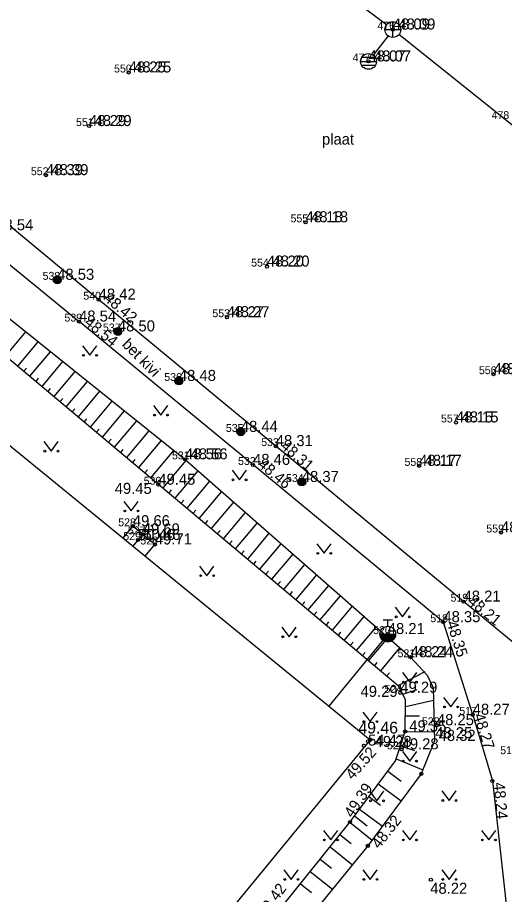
# Model space of a CAD drawing. Extents: x 640876 to 641418, y 6455595 to 6456085.
# Drawn here: x 641167 to 641197.9, y 6455921.6 to 6455977.1 of the extents above; entities that cross this region are included whole.
import ezdxf

# ---------------------------------------------------------------- set-up
doc = ezdxf.new("R2010")
doc.units = 0
for name, color, linetype in [('HALJASTUS', 7, 'Continuous'), ('HOONE', 7, 'Continuous'), ('HOONEDET', 7, 'Continuous'), ('KKAEV', 7, 'Continuous'), ('KORGUS', 7, 'Continuous'), ('MOOTKORG', 7, 'Continuous'), ('MOOTMPUNKT', 7, 'Continuous'), ('MOOTNR', 7, 'Continuous'), ('RAJATIS', 7, 'Continuous'), ('RELJEEF', 7, 'Continuous'), ('SKKAEV', 7, 'Continuous'), ('SKTRASS', 7, 'Continuous'), ('TEE', 7, 'Continuous'), ('VKAEV', 7, 'Continuous'), ('VTRASS', 7, 'Continuous')]:
    doc.layers.add(name, color=color, linetype=linetype)

msp = doc.modelspace()

# ---------------------------------------------------------------- linework, layer by layer
at = {"layer": 'HALJASTUS'}
for p, q in [((641171.149, 6455956.317), (641171.613, 6455955.71)), ((641171.613, 6455955.71), (641172.058, 6455956.317)), ((641175.644, 6455952.53), (641176.108, 6455951.923)), ((641176.108, 6455951.923), (641176.553, 6455952.53)), ((641168.705, 6455950.242), (641169.168, 6455949.635)), ((641169.168, 6455949.635), (641169.614, 6455950.242)), ((641180.612, 6455948.427), (641181.076, 6455947.82)), ((641181.076, 6455947.82), (641181.521, 6455948.427)), ((641173.77, 6455946.454), (641174.233, 6455945.847)), ((641174.233, 6455945.847), (641174.679, 6455946.454)), ((641185.975, 6455943.772), (641186.438, 6455943.165)), ((641186.438, 6455943.165), (641186.884, 6455943.772)), ((641178.562, 6455942.352), (641179.026, 6455941.745)), ((641179.026, 6455941.745), (641179.471, 6455942.352)), ((641190.943, 6455939.748), (641191.406, 6455939.141)), ((641191.406, 6455939.141), (641191.852, 6455939.748)), ((641183.767, 6455938.485), (641184.23, 6455937.879)), ((641184.23, 6455937.879), (641184.676, 6455938.485)), ((641191.394, 6455935.609), (641191.857, 6455935.002)), ((641191.857, 6455935.002), (641192.303, 6455935.609)), ((641194, 6455934.038), (641194.464, 6455933.431)), ((641194.464, 6455933.431), (641194.909, 6455934.038)), ((641188.894, 6455933.109), (641189.357, 6455932.502)), ((641189.357, 6455932.502), (641189.803, 6455933.109)), ((641191.394, 6455930.609), (641191.857, 6455930.002)), ((641191.857, 6455930.002), (641192.303, 6455930.609)), ((641189.312, 6455928.091), (641189.776, 6455927.484)), ((641189.776, 6455927.484), (641190.221, 6455928.091)), ((641193.894, 6455928.109), (641194.357, 6455927.502)), ((641194.357, 6455927.502), (641194.803, 6455928.109)), ((641186.394, 6455925.609), (641186.857, 6455925.002)), ((641186.857, 6455925.002), (641187.303, 6455925.609)), ((641191.394, 6455925.609), (641191.857, 6455925.002)), ((641191.857, 6455925.002), (641192.303, 6455925.609)), ((641196.394, 6455925.609), (641196.857, 6455925.002)), ((641196.857, 6455925.002), (641197.303, 6455925.609)), ((641183.894, 6455923.109), (641184.357, 6455922.502)), ((641184.357, 6455922.502), (641184.803, 6455923.109)), ((641188.894, 6455923.109), (641189.357, 6455922.502)), ((641189.357, 6455922.502), (641189.803, 6455923.109)), ((641193.894, 6455923.109), (641194.357, 6455922.502)), ((641194.357, 6455922.502), (641194.803, 6455923.109))]:
    msp.add_line(p, q, dxfattribs=at)
for centre in [(641171.212, 6455955.71), (641172.041, 6455955.71), (641175.707, 6455951.923), (641176.536, 6455951.923), (641168.767, 6455949.635), (641169.596, 6455949.635), (641180.675, 6455947.82), (641181.504, 6455947.82), (641173.832, 6455945.847), (641174.661, 6455945.847), (641186.037, 6455943.165), (641186.866, 6455943.165), (641178.625, 6455941.745), (641179.453, 6455941.745), (641191.005, 6455939.141), (641191.834, 6455939.141), (641183.829, 6455937.879), (641184.658, 6455937.879), (641191.456, 6455935.002), (641192.285, 6455935.002), (641194.063, 6455933.431), (641194.892, 6455933.431), (641188.956, 6455932.502), (641189.785, 6455932.502), (641191.456, 6455930.002), (641192.285, 6455930.002), (641189.375, 6455927.484), (641190.204, 6455927.484), (641193.956, 6455927.502), (641194.785, 6455927.502), (641186.456, 6455925.002), (641187.285, 6455925.002), (641191.456, 6455925.002), (641192.285, 6455925.002), (641196.456, 6455925.002), (641197.285, 6455925.002), (641183.956, 6455922.502), (641184.785, 6455922.502), (641188.956, 6455922.502), (641189.785, 6455922.502), (641193.956, 6455922.502), (641194.785, 6455922.502)]:
    msp.add_circle(centre, 0.055, dxfattribs=at)
at = {"layer": 'HOONE'}
msp.add_lwpolyline([(641149.742, 6455963.717), (641189.36, 6455931.349), (641178.797, 6455918.488), (641209.743, 6455893.117), (641188.509, 6455867.25), (641179.281, 6455874.809), (641167.4, 6455884.521), (641162.961, 6455888.191)], dxfattribs=at)
at = {"layer": 'HOONEDET'}
for p, q in [((641173.721, 6455944.126), (641174.337, 6455944.88)), ((641174.353, 6455943.609), (641174.968, 6455944.362)), ((641175.124, 6455942.98), (641175.733, 6455943.725))]:
    msp.add_line(p, q, dxfattribs=at)
msp.add_lwpolyline([(641175.733, 6455943.725), (641174.968, 6455944.362), (641174.337, 6455944.88)], dxfattribs=at)
at = {"layer": 'KKAEV'}
for p, q in [((641190.789, 6455975.847), (641190.789, 6455976.847)), ((641190.289, 6455976.347), (641191.289, 6455976.347))]:
    msp.add_line(p, q, dxfattribs=at)
msp.add_circle((641190.789, 6455976.347), 0.5, dxfattribs=at)
at = {"layer": 'KORGUS'}
for centre in [(641190.789, 6455976.347), (641189.249, 6455974.328), (641174.074, 6455973.628), (641171.565, 6455970.232), (641168.834, 6455967.121), (641185.267, 6455964.136), (641182.823, 6455961.331), (641172.174, 6455959.233), (641170.932, 6455957.845), (641180.293, 6455958.122), (641197.162, 6455954.513), (641194.786, 6455951.454), (641183.381, 6455949.957), (641177.637, 6455949.117), (641181.945, 6455948.764), (641192.454, 6455948.706), (641175.949, 6455947.51), (641197.632, 6455944.484), (641174.659, 6455944.006), (641195.267, 6455940.101), (641193.989, 6455938.801), (641191.912, 6455936.582), (641191.264, 6455934.33), (641195.845, 6455932.936), (641193.581, 6455932.275), (641189.36, 6455931.349), (641191.346, 6455930.747), (641192.589, 6455929.191), (641197.091, 6455928.74), (641188.083, 6455926.146), (641189.209, 6455924.627), (641193.194, 6455922.483)]:
    msp.add_circle(centre, 0.1, dxfattribs=at)
at = {"layer": 'MOOTMPUNKT'}
for centre in [(641190.789, 6455976.347), (641189.249, 6455974.328), (641174.074, 6455973.628), (641171.565, 6455970.232), (641168.834, 6455967.121), (641185.267, 6455964.136), (641182.823, 6455961.331), (641169.549, 6455960.492), (641172.174, 6455959.233), (641170.932, 6455957.845), (641180.293, 6455958.122), (641173.389, 6455957.223), (641197.162, 6455954.513), (641177.251, 6455954.084), (641194.786, 6455951.454), (641181.172, 6455950.858), (641183.381, 6455949.957), (641177.637, 6455949.117), (641181.945, 6455948.764), (641192.454, 6455948.706), (641175.949, 6455947.51), (641185.029, 6455947.682), (641174.337, 6455944.88), (641197.632, 6455944.484), (641174.659, 6455944.006), (641174.968, 6455944.362), (641175.733, 6455943.725), (641195.267, 6455940.101), (641193.989, 6455938.801), (641190.469, 6455938.047), (641191.912, 6455936.582), (641191.264, 6455934.33), (641195.845, 6455932.936), (641193.581, 6455932.275), (641191.568, 6455931.875), (641189.224, 6455931.251), (641188.96, 6455930.983), (641191.346, 6455930.747)]:
    msp.add_circle(centre, 0.1, dxfattribs=at)
at = {"layer": 'RAJATIS'}
for centre, radius in [((641169.549, 6455960.492), 0.25), ((641169.549, 6455960.492), 0.225), ((641169.549, 6455960.492), 0.2), ((641169.549, 6455960.492), 0.175), ((641169.549, 6455960.492), 0.15), ((641169.549, 6455960.492), 0.125), ((641169.549, 6455960.492), 0.1), ((641169.549, 6455960.492), 0.075), ((641169.549, 6455960.492), 0.05), ((641169.549, 6455960.492), 0.025), ((641173.389, 6455957.223), 0.25), ((641173.389, 6455957.223), 0.225), ((641173.389, 6455957.223), 0.2), ((641173.389, 6455957.223), 0.175), ((641173.389, 6455957.223), 0.15), ((641173.389, 6455957.223), 0.125), ((641173.389, 6455957.223), 0.1), ((641173.389, 6455957.223), 0.075), ((641173.389, 6455957.223), 0.05), ((641173.389, 6455957.223), 0.025), ((641177.251, 6455954.084), 0.25), ((641177.251, 6455954.084), 0.225), ((641177.251, 6455954.084), 0.2), ((641177.251, 6455954.084), 0.175), ((641177.251, 6455954.084), 0.15), ((641177.251, 6455954.084), 0.125), ((641177.251, 6455954.084), 0.1), ((641177.251, 6455954.084), 0.075), ((641177.251, 6455954.084), 0.05), ((641177.251, 6455954.084), 0.025), ((641181.172, 6455950.858), 0.25), ((641181.172, 6455950.858), 0.225), ((641181.172, 6455950.858), 0.2), ((641181.172, 6455950.858), 0.175), ((641181.172, 6455950.858), 0.15), ((641181.172, 6455950.858), 0.125), ((641181.172, 6455950.858), 0.1), ((641181.172, 6455950.858), 0.075), ((641181.172, 6455950.858), 0.05), ((641181.172, 6455950.858), 0.025), ((641185.029, 6455947.682), 0.25), ((641185.029, 6455947.682), 0.225), ((641185.029, 6455947.682), 0.2), ((641185.029, 6455947.682), 0.175), ((641185.029, 6455947.682), 0.15), ((641185.029, 6455947.682), 0.125), ((641185.029, 6455947.682), 0.1), ((641185.029, 6455947.682), 0.075), ((641185.029, 6455947.682), 0.05), ((641185.029, 6455947.682), 0.025)]:
    msp.add_circle(centre, radius, dxfattribs=at)
at = {"layer": 'RELJEEF'}
for p, q in [((641166.292, 6455955.669), (641167.57, 6455957.189)), ((641167.058, 6455955.025), (641168.35, 6455956.563)), ((641167.824, 6455954.382), (641169.131, 6455955.937)), ((641168.589, 6455953.739), (641169.911, 6455955.312)), ((641167.441, 6455954.704), (641167.602, 6455954.895)), ((641169.355, 6455953.095), (641170.691, 6455954.686)), ((641168.207, 6455954.06), (641168.367, 6455954.252)), ((641170.121, 6455952.452), (641171.472, 6455954.06)), ((641168.972, 6455953.417), (641169.133, 6455953.608)), ((641170.886, 6455951.809), (641172.252, 6455953.434)), ((641169.738, 6455952.774), (641169.899, 6455952.965)), ((641170.503, 6455952.13), (641170.664, 6455952.322)), ((641171.652, 6455951.166), (641173.032, 6455952.809)), ((641172.417, 6455950.522), (641173.813, 6455952.183)), ((641171.269, 6455951.487), (641171.43, 6455951.679)), ((641173.183, 6455949.879), (641174.593, 6455951.557)), ((641172.035, 6455950.844), (641172.195, 6455951.035)), ((641173.949, 6455949.236), (641175.374, 6455950.932)), ((641172.8, 6455950.201), (641172.961, 6455950.392)), ((641174.714, 6455948.592), (641176.154, 6455950.306)), ((641173.566, 6455949.557), (641173.727, 6455949.749)), ((641175.48, 6455947.949), (641176.934, 6455949.68)), ((641174.332, 6455948.914), (641174.492, 6455949.105)), ((641176.246, 6455947.306), (641177.712, 6455949.051)), ((641175.097, 6455948.271), (641175.258, 6455948.462)), ((641177.011, 6455946.663), (641178.464, 6455948.391)), ((641175.863, 6455947.627), (641176.024, 6455947.819)), ((641177.777, 6455946.019), (641179.215, 6455947.731)), ((641176.628, 6455946.984), (641176.789, 6455947.176)), ((641178.542, 6455945.376), (641179.967, 6455947.071)), ((641177.394, 6455946.341), (641177.555, 6455946.532)), ((641179.308, 6455944.733), (641180.718, 6455946.411)), ((641178.16, 6455945.698), (641178.32, 6455945.889)), ((641180.074, 6455944.089), (641181.47, 6455945.751)), ((641178.925, 6455945.054), (641179.086, 6455945.246)), ((641180.839, 6455943.446), (641182.222, 6455945.091)), ((641179.691, 6455944.411), (641179.852, 6455944.602)), ((641181.605, 6455942.803), (641182.973, 6455944.431)), ((641180.457, 6455943.768), (641180.617, 6455943.959)), ((641182.371, 6455942.16), (641183.725, 6455943.771)), ((641181.222, 6455943.124), (641181.383, 6455943.316)), ((641183.136, 6455941.516), (641184.476, 6455943.111)), ((641181.988, 6455942.481), (641182.149, 6455942.673)), ((641183.902, 6455940.873), (641185.228, 6455942.451)), ((641182.753, 6455941.838), (641182.914, 6455942.029)), ((641184.667, 6455940.23), (641185.98, 6455941.791)), ((641183.519, 6455941.195), (641183.68, 6455941.386)), ((641184.285, 6455940.551), (641184.445, 6455940.743)), ((641185.433, 6455939.586), (641186.731, 6455941.131)), ((641185.05, 6455939.908), (641185.211, 6455940.099)), ((641186.199, 6455938.943), (641187.483, 6455940.471)), ((641186.964, 6455938.3), (641188.235, 6455939.811)), ((641185.816, 6455939.265), (641185.977, 6455939.456)), ((641187.73, 6455937.656), (641188.986, 6455939.152)), ((641186.582, 6455938.621), (641186.742, 6455938.813)), ((641188.496, 6455937.013), (641189.738, 6455938.492)), ((641187.347, 6455937.978), (641187.508, 6455938.17)), ((641188.113, 6455937.335), (641188.274, 6455937.526)), ((641189.261, 6455936.37), (641190.489, 6455937.832)), ((641188.878, 6455936.692), (641189.039, 6455936.883)), ((641190.027, 6455935.727), (641191.241, 6455937.172)), ((641189.644, 6455936.048), (641189.805, 6455936.24)), ((641191.133, 6455934.796), (641192.837, 6455935.678)), ((641190.41, 6455935.405), (641190.571, 6455935.596)), ((641191.415, 6455934.251), (641192.328, 6455934.533)), ((641191.588, 6455933.464), (641193.365, 6455933.853)), ((641191.58, 6455932.875), (641192.484, 6455932.864)), ((641191.568, 6455931.875), (641193.412, 6455931.852)), ((641191.268, 6455930.971), (641192.166, 6455930.673)), ((641190.994, 6455930.146), (641192.691, 6455929.445)), ((641190.463, 6455929.361), (641191.309, 6455928.734)), ((641189.868, 6455928.557), (641191.322, 6455927.48)), ((641189.273, 6455927.753), (641190, 6455927.215)), ((641188.678, 6455926.95), (641190.132, 6455925.873)), ((641188.361, 6455926.522), (641189.169, 6455925.902)), ((641188.069, 6455926.129), (641189.482, 6455924.996)), ((641187.444, 6455925.349), (641188.155, 6455924.778)), ((641186.818, 6455924.568), (641188.235, 6455923.433)), ((641186.193, 6455923.788), (641186.898, 6455923.223)), ((641185.567, 6455923.008), (641186.971, 6455921.883)), ((641184.942, 6455922.228), (641185.64, 6455921.668))]:
    msp.add_line(p, q, dxfattribs=at)
for points in [[(641151.026, 6455962.667), (641152.889, 6455965.903), (641154.684, 6455966.138), (641158.993, 6455964.066), (641177.637, 6455949.117), (641191.912, 6455936.582), (641192.954, 6455935.439), (641193.346, 6455934.637), (641193.426, 6455931.281), (641192.589, 6455929.191), (641189.209, 6455924.627), (641185.194, 6455919.704), (641183.118, 6455916.876)], [(641151.64, 6455962.166), (641152.931, 6455964.438), (641155.056, 6455964.795), (641158.507, 6455962.239), (641160.822, 6455960.264), (641191.133, 6455934.798)], [(641180.696, 6455916.931), (641183.691, 6455920.667), (641188.083, 6455926.146), (641190.953, 6455930.022), (641191.568, 6455931.875), (641191.593, 6455933.908), (641191.133, 6455934.798)]]:
    msp.add_lwpolyline(points, dxfattribs=at)
at = {"layer": 'SKKAEV'}
for p, q in [((641189.679, 6455974.578), (641188.819, 6455974.578)), ((641188.749, 6455974.328), (641189.749, 6455974.328)), ((641189.679, 6455974.078), (641188.819, 6455974.078))]:
    msp.add_line(p, q, dxfattribs=at)
msp.add_circle((641189.249, 6455974.328), 0.5, dxfattribs=at)
at = {"layer": 'SKTRASS'}
for points in [[(641190.389, 6455976.647), (641177.941, 6455985.97)], [(641190.486, 6455975.949), (641189.552, 6455974.726)], [(641203.6, 6455966.097), (641191.18, 6455976.034)]]:
    msp.add_lwpolyline(points, dxfattribs=at)
at = {"layer": 'TEE'}
for points in [[(641219.562, 6455985.852), (641216.822, 6455976.794), (641214.309, 6455968.346), (641210.175, 6455958.541), (641206.979, 6455950.86), (641202.453, 6455940.169), (641200.572, 6455935.729), (641195.267, 6455940.101), (641183.381, 6455949.957), (641172.174, 6455959.233), (641160.995, 6455968.496)], [(641149.551, 6455965.734), (641152.24, 6455967.045), (641153.501, 6455967.653), (641158.352, 6455968.119), (641159.124, 6455967.526), (641170.932, 6455957.845)], [(641195.845, 6455932.936), (641193.989, 6455938.801), (641181.945, 6455948.764), (641170.932, 6455957.845)], [(641195.845, 6455932.936), (641197.091, 6455928.74), (641198.157, 6455919.205), (641198.959, 6455910.955), (641196.671, 6455908.21)]]:
    msp.add_lwpolyline(points, dxfattribs=at)
at = {"layer": 'VKAEV'}
for p, q in [((641190.169, 6455938.947), (641190.769, 6455938.947)), ((641190.469, 6455938.547), (641190.469, 6455938.947)), ((641189.969, 6455938.047), (641190.969, 6455938.047))]:
    msp.add_line(p, q, dxfattribs=at)
msp.add_circle((641190.469, 6455938.047), 0.5, dxfattribs=at)
for radius in [0.475, 0.45, 0.425, 0.4, 0.375, 0.35, 0.325, 0.3, 0.275, 0.25, 0.225, 0.2, 0.175, 0.15, 0.125, 0.1, 0.075, 0.05]:
    msp.add_arc((641190.469, 6455938.047), radius, 180, 0, dxfattribs=at)
at = {"layer": 'VTRASS'}
msp.add_lwpolyline([(641190.469, 6455938.047), (641186.745, 6455933.486)], dxfattribs=at)

# ---------------------------------------------------------------- texts
at = {"layer": 'KORGUS'}
for s, height, p in [('48.09', 0.7, (641191.139, 6455976.347)), ('48.07', 0.7, (641189.599, 6455974.328)), ('48.25', 0.7, (641174.424, 6455973.628)), ('48.29', 0.7, (641171.915, 6455970.232)), ('48.39', 0.7, (641169.184, 6455967.121)), ('48.18', 0.7, (641185.617, 6455964.136)), ('48.20', 0.7, (641183.173, 6455961.331)), ('48.27', 0.7, (641180.643, 6455958.122)), ('48.15', 0.7, (641197.512, 6455954.513)), ('48.15', 0.7, (641195.136, 6455951.454)), ('48.56', 0.7, (641177.987, 6455949.117)), ('48.17', 0.7, (641192.804, 6455948.706)), ('49.45', 0.7, (641173.19, 6455946.929)), ('50.46', 0.7, (641175.009, 6455944.006)), ('48.24', 0.7, (641192.262, 6455936.582)), ('49.29', 0.7, (641188.747, 6455934.069)), ('49.46', 0.75, (641188.608, 6455931.744)), ('48.25', 0.7, (641193.475, 6455931.45)), ('49.28', 0.7, (641189.636, 6455930.894)), (' 48.22', 0.7, (641192.896, 6455921.594))]:
    msp.add_text(s, height=height, dxfattribs=at).set_placement(p)
for s, rotation, p in [('48.42', 319.6202, (641172.451, 6455959.227)), ('48.54', 320.6971, (641171.216, 6455957.693)), ('48.31', 318.9871, (641183.639, 6455949.857)), ('48.46', 319.9337, (641182.195, 6455948.702)), ('48.21', 321.0479, (641195.475, 6455940.007)), ('48.35', 287.4869, (641194.186, 6455938.762)), ('48.27', 287.0974, (641195.899, 6455932.913)), (' 49.52', 48.4564, (641188.07, 6455928.566)), (' 49.39', 55.9076, (641188.083, 6455926.146)), (' 48.24', 274.847, (641197.151, 6455928.887)), (' 48.32', 51.482, (641189.757, 6455924.191)), (' 49.42', 53.5795, (641182.554, 6455919.833))]:
    msp.add_text(s, height=0.7, rotation=rotation, dxfattribs=at).set_placement(p)
at = {"layer": 'MOOTKORG'}
for s, p in [('48.09', (641190.789, 6455976.347)), ('48.07', (641189.249, 6455974.328)), ('48.25', (641174.074, 6455973.628)), ('48.29', (641171.565, 6455970.232)), ('48.39', (641168.834, 6455967.121)), ('48.18', (641185.267, 6455964.136)), ('48.54', (641165.694, 6455963.626)), ('48.20', (641182.823, 6455961.331)), ('48.53', (641169.549, 6455960.492)), ('48.42', (641172.174, 6455959.233)), ('48.54', (641170.932, 6455957.845)), ('48.27', (641180.293, 6455958.122)), ('48.50', (641173.389, 6455957.223)), ('48.15', (641197.162, 6455954.513)), ('48.48', (641177.251, 6455954.084)), ('48.15', (641194.786, 6455951.454)), ('48.44', (641181.172, 6455950.858)), ('48.31', (641183.381, 6455949.957)), ('48.56', (641177.637, 6455949.117)), ('48.46', (641181.945, 6455948.764)), ('48.17', (641192.454, 6455948.706)), ('49.45', (641175.949, 6455947.51)), ('48.37', (641185.029, 6455947.682)), ('49.66', (641174.337, 6455944.88)), ('48.17', (641197.632, 6455944.484)), ('50.46', (641174.659, 6455944.006)), ('49.69', (641174.968, 6455944.362)), ('49.71', (641175.733, 6455943.725)), ('48.21', (641195.267, 6455940.101)), ('48.35', (641193.989, 6455938.801)), ('48.21', (641190.469, 6455938.047)), ('48.24', (641191.912, 6455936.582)), ('49.29', (641191.264, 6455934.33)), ('48.27', (641195.845, 6455932.936)), ('48.25', (641193.581, 6455932.275)), (' 49.35', (641191.568, 6455931.875)), (' 48.32', (641193.426, 6455931.281)), (' 54.47', (641188.96, 6455930.983)), ('49.28', (641191.346, 6455930.747))]:
    msp.add_text(s, height=0.7, dxfattribs=at).set_placement(p)
at = {"layer": 'MOOTNR'}
for s, p in [('476', (641189.814, 6455976.347)), ('477', (641188.249, 6455974.328)), ('550', (641173.149, 6455973.628)), ('551', (641170.74, 6455970.232)), ('478', (641197.041, 6455970.676)), ('552', (641167.884, 6455967.121)), ('555', (641184.317, 6455964.136)), ('554', (641181.823, 6455961.331)), ('538', (641168.624, 6455960.492)), ('540', (641171.2, 6455959.233)), ('553', (641179.368, 6455958.122)), ('539', (641170.007, 6455957.845)), ('537', (641172.439, 6455957.223)), ('536', (641176.326, 6455954.084)), ('556', (641196.237, 6455954.513)), ('557', (641193.836, 6455951.454)), ('535', (641180.222, 6455950.858)), ('533', (641182.456, 6455949.957)), ('531', (641176.812, 6455949.117)), ('532', (641180.995, 6455948.764)), ('558', (641191.529, 6455948.706)), ('530', (641175.024, 6455947.51)), ('534', (641184.029, 6455947.682)), ('528', (641173.412, 6455944.88)), ('527', (641174.018, 6455944.362)), ('559', (641196.707, 6455944.484)), ('529', (641173.734, 6455944.006)), ('526', (641174.808, 6455943.725)), ('519', (641194.442, 6455940.101)), ('518', (641193.164, 6455938.801)), ('520', (641189.544, 6455938.047)), ('521', (641191.087, 6455936.582)), ('524', (641190.265, 6455934.33)), ('517', (641194.995, 6455932.936)), ('522', (641192.631, 6455932.275)), ('523', (641190.421, 6455930.747)), ('515', (641197.584, 6455930.44))]:
    msp.add_text(s, height=0.5, dxfattribs=at).set_placement(p)
at = {"layer": 'TEE'}
msp.add_text('plaat', height=0.7, dxfattribs=at).set_placement((641186.306, 6455969.058))
msp.add_text('bet kivi', height=0.7, rotation=314.589, dxfattribs=at).set_placement((641173.6, 6455956.355))

doc.saveas('drawing.dxf')
